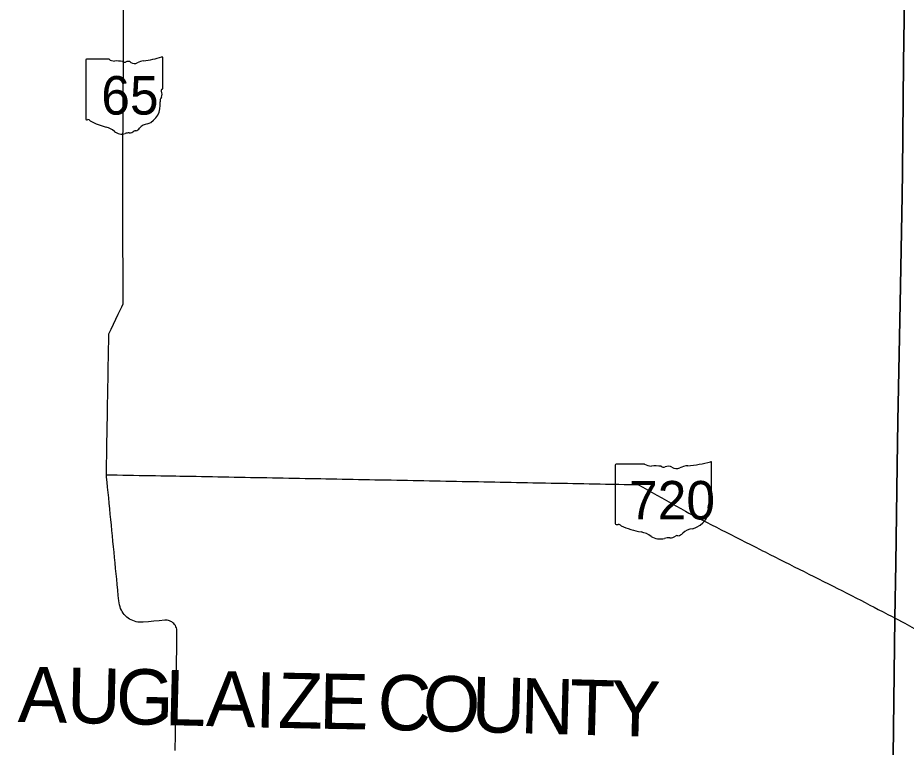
# Model space of a CAD drawing. Extents: x 0 to 34, y 0 to 22.
# Drawn here: x 6.011 to 6.269, y 19.3992 to 19.6111 of the extents above; entities that cross this region are included whole.
import ezdxf

# ---------------------------------------------------------------- set-up
doc = ezdxf.new("R2010")
doc.units = 0
for name, color, linetype in [('GM_X_County', 7, 'Continuous'), ('GM_X_County_Text', 7, 'Continuous'), ('GM_X_State_Location', 7, 'Continuous'), ('GM_X_State_Route', 7, 'Continuous'), ('GM_X_State_Shield', 7, 'Continuous')]:
    doc.layers.add(name, color=color, linetype=linetype)

msp = doc.modelspace()

# ---------------------------------------------------------------- linework, layer by layer
at = {"layer": 'GM_X_County'}
for points in [[(6.224545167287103, 19.175843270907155), (6.225083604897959, 19.219057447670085), (6.226321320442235, 19.304449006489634), (6.226424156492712, 19.311436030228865), (6.227034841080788, 19.389227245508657), (6.237472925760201, 19.389264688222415), (6.265053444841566, 19.38859652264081), (6.265712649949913, 19.43672940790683), (6.2660032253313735, 19.452577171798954), (6.266360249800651, 19.481082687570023), (6.2665922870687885, 19.493925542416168), (6.267210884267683, 19.52817666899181), (6.267798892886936, 19.559429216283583), (6.26790225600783, 19.566442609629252), (6.268171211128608, 19.597972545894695), (6.268916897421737, 19.643535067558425)], [(6.268916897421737, 19.643535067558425), (6.268171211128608, 19.597972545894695), (6.26790225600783, 19.566442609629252), (6.267798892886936, 19.559429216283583), (6.267210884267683, 19.52817666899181), (6.2665922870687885, 19.493925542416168), (6.266360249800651, 19.481082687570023), (6.2660032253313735, 19.452577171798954), (6.265712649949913, 19.43672940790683), (6.265053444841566, 19.38859652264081)]]:
    msp.add_lwpolyline(points, dxfattribs=at)
at = {"layer": 'GM_X_State_Route'}
for points in [[(6.056752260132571, 19.398250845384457), (6.056775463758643, 19.399832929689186), (6.056798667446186, 19.401415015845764), (6.056821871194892, 19.40299710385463), (6.056845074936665, 19.404579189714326), (6.056868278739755, 19.40616127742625), (6.056891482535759, 19.407743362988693), (6.0569146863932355, 19.40932545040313), (6.056937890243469, 19.410907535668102), (6.05696109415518, 19.41248962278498), (6.056984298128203, 19.414071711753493), (6.057007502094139, 19.415653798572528), (6.057030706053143, 19.41723588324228), (6.057053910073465, 19.418817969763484), (6.057077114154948, 19.420400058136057), (6.057100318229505, 19.421982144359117), (6.057123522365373, 19.423564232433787), (6.05714672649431, 19.425146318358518), (6.057169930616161, 19.426728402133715), (6.0571931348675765, 19.42831049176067), (6.057215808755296, 19.429892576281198), (6.057237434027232, 19.431362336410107), (6.057258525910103, 19.43283262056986), (6.057243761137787, 19.433197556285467), (6.05718891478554, 19.433558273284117), (6.057093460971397, 19.43391055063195), (6.0569595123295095, 19.434249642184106), (6.056788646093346, 19.434572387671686), (6.056582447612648, 19.434873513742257), (6.056344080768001, 19.435149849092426), (6.056076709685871, 19.435398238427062), (6.05578296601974, 19.435614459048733), (6.055467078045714, 19.435797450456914), (6.055132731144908, 19.435943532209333), (6.054784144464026, 19.436051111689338), (6.054425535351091, 19.436119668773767), (6.054061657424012, 19.436147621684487), (6.053696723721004, 19.43613443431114), (6.052121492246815, 19.435989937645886), (6.050546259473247, 19.43584544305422), (6.04898790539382, 19.43570252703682), (6.0474290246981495, 19.435560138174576), (6.046918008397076, 19.43553376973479), (6.046406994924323, 19.435548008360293), (6.045898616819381, 19.435603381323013), (6.045396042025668, 19.43569883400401), (6.044902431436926, 19.435833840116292), (6.044421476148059, 19.43600786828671), (6.043956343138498, 19.436219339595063), (6.043509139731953, 19.436467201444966), (6.0430830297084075, 19.43675039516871), (6.0426806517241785, 19.437066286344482), (6.042304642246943, 19.437413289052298), (6.041957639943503, 19.437788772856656), (6.041641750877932, 19.438191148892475), (6.0413590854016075, 19.438616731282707), (6.041110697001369, 19.439063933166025), (6.04089922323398, 19.439529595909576), (6.040725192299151, 19.440010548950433), (6.040566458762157, 19.440579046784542), (6.040447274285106, 19.441157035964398), (6.040369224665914, 19.441741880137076), (6.040214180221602, 19.443316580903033), (6.040059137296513, 19.44489128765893), (6.03990409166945, 19.446465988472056), (6.039749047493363, 19.448040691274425), (6.039594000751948, 19.449615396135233), (6.039438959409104, 19.451190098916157), (6.039283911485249, 19.452764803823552), (6.039128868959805, 19.45433950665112), (6.038973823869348, 19.455914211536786), (6.038818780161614, 19.45748891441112), (6.038663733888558, 19.459063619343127), (6.038508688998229, 19.460638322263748), (6.038353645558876, 19.462213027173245), (6.038198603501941, 19.46378773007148), (6.038043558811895, 19.465362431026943), (6.03788851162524, 19.466937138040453), (6.037732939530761, 19.468511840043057), (6.037577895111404, 19.470086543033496), (6.037422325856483, 19.471661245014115), (6.037267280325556, 19.473235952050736), (6.0371117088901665, 19.474810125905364), (6.036970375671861, 19.476245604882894), (6.036828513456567, 19.477681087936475), (6.036760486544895, 19.47837614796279), (6.036768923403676, 19.478866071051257), (6.036796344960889, 19.480448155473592), (6.03682376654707, 19.4820302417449), (6.036851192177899, 19.483612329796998), (6.036878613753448, 19.485194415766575), (6.036906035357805, 19.486776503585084), (6.0369334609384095, 19.488358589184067), (6.036960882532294, 19.489940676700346), (6.036988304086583, 19.491522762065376), (6.037015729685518, 19.49310484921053), (6.037043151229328, 19.494686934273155), (6.0370705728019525, 19.49626902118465), (6.037097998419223, 19.497851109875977), (6.037125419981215, 19.49943319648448), (6.037152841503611, 19.5010152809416), (6.037180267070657, 19.50259736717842), (6.037208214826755, 19.504179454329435), (6.037235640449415, 19.505761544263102), (6.03726358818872, 19.507343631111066), (6.037291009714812, 19.50892571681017), (6.037318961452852, 19.510507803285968), (6.037346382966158, 19.51208988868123), (6.037374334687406, 19.51367197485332), (6.037401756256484, 19.51525406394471), (6.037429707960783, 19.51683614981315), (6.0374508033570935, 19.51806173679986), (6.037472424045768, 19.519286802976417), (6.038155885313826, 19.520713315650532), (6.0388393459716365, 19.522139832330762), (6.039522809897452, 19.523566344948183), (6.040206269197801, 19.524992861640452), (6.040889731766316, 19.526419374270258), (6.0412667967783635, 19.527205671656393), (6.041643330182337, 19.527991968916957), (6.041635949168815, 19.529574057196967), (6.041628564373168, 19.531156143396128), (6.041621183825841, 19.532738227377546), (6.041613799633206, 19.534320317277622), (6.041606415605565, 19.53590240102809), (6.041599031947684, 19.537484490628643), (6.041591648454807, 19.539066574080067), (6.04158426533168, 19.54064866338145), (6.0415768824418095, 19.542230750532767), (6.041569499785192, 19.543812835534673), (6.041562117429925, 19.545394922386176), (6.041554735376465, 19.546977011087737), (6.0415478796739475, 19.548559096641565), (6.041540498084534, 19.550141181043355), (6.041533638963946, 19.551723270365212), (6.041526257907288, 19.553305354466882), (6.04151940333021, 19.554887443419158), (6.041512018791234, 19.556469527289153), (6.041505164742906, 19.558051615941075), (6.04149778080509, 19.559633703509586), (6.041490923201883, 19.561215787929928), (6.041487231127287, 19.564312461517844), (6.041498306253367, 19.565894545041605), (6.041509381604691, 19.567476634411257), (6.041520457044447, 19.56905872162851), (6.04153153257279, 19.570640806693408), (6.041542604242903, 19.572222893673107), (6.041553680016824, 19.573804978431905), (6.041564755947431, 19.575387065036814), (6.041575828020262, 19.576969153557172), (6.041586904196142, 19.578551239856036), (6.041597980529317, 19.580133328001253), (6.041609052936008, 19.58171541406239), (6.041620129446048, 19.5832974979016), (6.041631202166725, 19.584879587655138), (6.041642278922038, 19.586461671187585), (6.041653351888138, 19.588043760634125), (6.04166442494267, 19.58962584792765), (6.041675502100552, 19.591207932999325), (6.041686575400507, 19.592790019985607), (6.041697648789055, 19.594372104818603), (6.041708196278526, 19.595954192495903), (6.041719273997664, 19.597536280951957), (6.041729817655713, 19.599118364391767), (6.0417408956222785, 19.60070045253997), (6.041751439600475, 19.602282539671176), (6.041762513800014, 19.603864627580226), (6.041769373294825, 19.604840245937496), (6.041775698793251, 19.60581586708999), (6.041788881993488, 19.691094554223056)], [(6.036760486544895, 19.47837614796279), (6.03834257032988, 19.478349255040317), (6.039924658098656, 19.47832236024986), (6.041506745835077, 19.478295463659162), (6.043088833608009, 19.478268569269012), (6.04467091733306, 19.47824167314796), (6.046253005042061, 19.478214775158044), (6.047835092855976, 19.478187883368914), (6.049417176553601, 19.478160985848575), (6.050999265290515, 19.478134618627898), (6.052581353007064, 19.478107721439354), (6.054163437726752, 19.478081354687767), (6.055745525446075, 19.478054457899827), (6.056905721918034, 19.478034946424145), (6.058065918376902, 19.4780154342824), (6.059647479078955, 19.477985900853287), (6.061229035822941, 19.477956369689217), (6.062810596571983, 19.477926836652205), (6.064392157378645, 19.47789730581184), (6.065973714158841, 19.4778677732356), (6.0675552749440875, 19.477838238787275), (6.069136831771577, 19.477808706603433), (6.070718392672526, 19.477779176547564), (6.072299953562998, 19.477749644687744), (6.0738815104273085, 19.47772011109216), (6.075463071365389, 19.47769057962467), (6.077044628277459, 19.47766104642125), (6.078626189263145, 19.477631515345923), (6.080207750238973, 19.47760198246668), (6.081789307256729, 19.477572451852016), (6.083370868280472, 19.47754291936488), (6.084952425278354, 19.477513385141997), (6.086533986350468, 19.477483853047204), (6.088115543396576, 19.477454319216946), (6.08969710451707, 19.477424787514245), (6.09127866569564, 19.47739525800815), (6.092860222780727, 19.477365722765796), (6.094441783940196, 19.47733618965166), (6.096023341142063, 19.477306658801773), (6.097604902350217, 19.477277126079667), (6.099049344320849, 19.477250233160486), (6.100493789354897, 19.477222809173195), (6.102075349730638, 19.477192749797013), (6.1036569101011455, 19.47716268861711), (6.105238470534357, 19.47713262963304), (6.106820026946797, 19.4771025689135), (6.108401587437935, 19.47707251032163), (6.109983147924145, 19.477042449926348), (6.11156470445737, 19.4770123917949), (6.113146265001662, 19.476982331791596), (6.114727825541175, 19.476952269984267), (6.116309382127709, 19.476922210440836), (6.1178909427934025, 19.476892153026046), (6.119472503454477, 19.476862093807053), (6.121054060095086, 19.476832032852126), (6.122635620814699, 19.47680197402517), (6.12421718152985, 19.476771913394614), (6.125798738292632, 19.476741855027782), (6.12738029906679, 19.476711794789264), (6.128961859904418, 19.47668173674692), (6.130543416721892, 19.47665167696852), (6.1321249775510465, 19.476621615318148), (6.133706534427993, 19.47659155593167), (6.135288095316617, 19.47656149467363), (6.136869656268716, 19.476531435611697), (6.138451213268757, 19.476501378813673), (6.140032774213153, 19.476471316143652), (6.141614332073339, 19.476441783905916), (6.143195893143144, 19.47641172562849), (6.144777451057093, 19.476382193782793), (6.146359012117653, 19.476352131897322), (6.147940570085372, 19.47632260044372), (6.149522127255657, 19.476292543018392), (6.151103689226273, 19.47626300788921), (6.152685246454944, 19.47623295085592), (6.154266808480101, 19.476203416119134), (6.155848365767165, 19.476173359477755), (6.157429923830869, 19.476143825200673), (6.159011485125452, 19.476113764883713), (6.160593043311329, 19.476084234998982), (6.16217460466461, 19.476054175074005), (6.163230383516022, 19.476034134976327), (6.1642861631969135, 19.476014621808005), (6.165867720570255, 19.475984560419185), (6.167449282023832, 19.475954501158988), (6.169030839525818, 19.4759244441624), (6.170612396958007, 19.47589438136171), (6.172193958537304, 19.475864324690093), (6.173775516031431, 19.47583426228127), (6.17535707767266, 19.475804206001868), (6.176938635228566, 19.475774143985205), (6.178520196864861, 19.475744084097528), (6.180101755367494, 19.475714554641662), (6.181683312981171, 19.475684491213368), (6.183264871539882, 19.47565496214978), (6.184411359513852, 19.475633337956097), (6.1855578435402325, 19.475611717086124), (6.187139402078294, 19.475582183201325), (6.188720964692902, 19.47555265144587), (6.18990541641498, 19.47553050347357), (6.191089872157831, 19.475508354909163), (6.192471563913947, 19.47473787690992), (6.193853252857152, 19.47396740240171), (6.195234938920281, 19.473196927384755), (6.196616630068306, 19.472426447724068), (6.19799831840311, 19.471655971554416), (6.199380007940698, 19.470885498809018), (6.200761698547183, 19.47011502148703), (6.202143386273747, 19.469344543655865), (6.203525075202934, 19.468574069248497), (6.204907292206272, 19.467804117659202), (6.205861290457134, 19.467272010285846), (6.206815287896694, 19.466740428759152), (6.208225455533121, 19.466022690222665), (6.209635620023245, 19.46530495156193), (6.211045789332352, 19.46458720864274), (6.2124559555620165, 19.463869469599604), (6.213866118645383, 19.463151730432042), (6.2152762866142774, 19.462433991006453), (6.216686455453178, 19.461716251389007), (6.218096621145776, 19.46099851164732), (6.219506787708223, 19.460280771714), (6.2209169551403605, 19.45956303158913), (6.222327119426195, 19.45884529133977), (6.223737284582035, 19.458127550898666), (6.22514745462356, 19.457409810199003), (6.226557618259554, 19.456692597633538), (6.227287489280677, 19.456320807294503), (6.228017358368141, 19.455949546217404), (6.229430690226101, 19.455238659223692), (6.230844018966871, 19.45452777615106), (6.232257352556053, 19.45381689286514), (6.233670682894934, 19.45310600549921), (6.23508401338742, 19.452394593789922), (6.236497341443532, 19.451683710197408), (6.237910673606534, 19.450972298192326), (6.239324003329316, 19.450261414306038), (6.24073733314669, 19.44955000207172), (6.242150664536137, 19.44883911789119), (6.243563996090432, 19.448127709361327), (6.2449773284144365, 19.447416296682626), (6.246390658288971, 19.446705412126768), (6.247803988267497, 19.445993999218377), (6.2490490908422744, 19.445367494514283), (6.250294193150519, 19.44474098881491), (6.251703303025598, 19.444021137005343), (6.25177744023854, 19.44398325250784)], [(6.25177744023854, 19.44398325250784), (6.253111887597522, 19.443301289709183), (6.254521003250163, 19.442581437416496), (6.255787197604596, 19.441934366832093), (6.257053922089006, 19.441287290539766), (6.258450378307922, 19.44054424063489), (6.259660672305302, 19.439900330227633), (6.260871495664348, 19.439255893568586), (6.262276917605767, 19.438529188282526), (6.263682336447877, 19.437802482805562), (6.264679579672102, 19.43728725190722), (6.265766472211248, 19.43675672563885)], [(6.265766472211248, 19.43675672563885), (6.2685720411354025, 19.435230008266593), (6.271969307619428, 19.433355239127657)]]:
    msp.add_lwpolyline(points, dxfattribs=at)
at = {"layer": 'GM_X_State_Shield'}
for p, q in [((6.030746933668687, 19.59879273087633), (6.030746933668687, 19.581808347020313)), ((6.037520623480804, 19.59908496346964), (6.030967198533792, 19.59908496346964)), ((6.053124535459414, 19.590621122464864), (6.053124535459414, 19.59950586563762)), ((6.0531223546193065, 19.59062330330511), (6.053124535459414, 19.590621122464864)), ((6.192994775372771, 19.481468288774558), (6.184802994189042, 19.481468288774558)), ((6.212499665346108, 19.47300444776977), (6.212499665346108, 19.481889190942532)), ((6.184527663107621, 19.481176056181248), (6.184527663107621, 19.46419167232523)), ((6.212496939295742, 19.473006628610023), (6.212499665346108, 19.47300444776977))]:
    msp.add_line(p, q, dxfattribs=at)
for centre, radius, start, end in [((6.0310032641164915, 19.59882889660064), 0.0002592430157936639, 98.1301027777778, 188.13010277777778), ((6.039081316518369, 19.601056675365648), 0.0025145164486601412, 231.61950555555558, 271.11188333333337), ((6.039915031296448, 19.58954973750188), 0.009027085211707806, 80.48669166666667, 94.98826944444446), ((6.041964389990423, 19.598916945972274), 0.0007254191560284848, 219.79206111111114, 297.1023694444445), ((6.043029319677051, 19.59695387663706), 0.0015082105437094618, 54.466683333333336, 119.14113055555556), ((6.044975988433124, 19.599646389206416), 0.0018143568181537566, 233.85620555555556, 294.82819166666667), ((6.0481802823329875, 19.593897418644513), 0.004774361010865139, 97.34618055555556, 120.7688527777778), ((6.045153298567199, 19.622240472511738), 0.02373123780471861, 275.8444694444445, 288.9064527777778), ((6.052876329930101, 19.599542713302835), 0.000249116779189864, 351.8620861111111, 97.738), ((6.053066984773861, 19.5899688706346), 0.00038552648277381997, 107.94398333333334, 210.33696666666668), ((6.050614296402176, 19.588845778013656), 0.002314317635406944, 340.0329638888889, 23.649566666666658), ((6.052858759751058, 19.59058679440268), 0.0002666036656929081, 289.6038111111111, 7.734130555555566), ((6.054017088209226, 19.58690296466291), 0.001683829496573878, 136.80649722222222, 186.92959444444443), ((6.046482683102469, 19.58577270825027), 0.005935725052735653, 292.3088861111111, 8.985838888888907), ((6.03100559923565, 19.58177116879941), 0.00026154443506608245, 171.9583861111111, 258.30661388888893), ((6.031045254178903, 19.58350880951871), 0.0019959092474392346, 267.33899444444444, 280.6038555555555), ((6.031453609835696, 19.58082847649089), 0.000719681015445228, 29.748380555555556, 93.27174722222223), ((6.040539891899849, 19.59608823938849), 0.017137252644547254, 240.41292222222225, 257.1985), ((6.035430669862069, 19.57417805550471), 0.0053619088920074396, 47.184155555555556, 75.83597222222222), ((6.048985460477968, 19.577040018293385), 0.0032508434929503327, 94.40312222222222, 142.57675), ((6.041229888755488, 19.580744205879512), 0.003402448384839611, 230.70037222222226, 286.29183611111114), ((6.043195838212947, 19.574872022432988), 0.0027957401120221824, 85.69512222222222, 111.20994722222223), ((6.043444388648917, 19.579472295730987), 0.0018128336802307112, 268.7770194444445, 315.54927222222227), ((6.045084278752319, 19.577827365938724), 0.0005103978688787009, 65.75173055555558, 132.64842222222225), ((6.044866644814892, 19.58016222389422), 0.0019176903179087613, 282.8731916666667, 323.27711111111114)]:
    msp.add_arc(centre, radius, start, end, dxfattribs=at)
for centre, major_axis, ratio, start_param, end_param in [((6.184848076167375, 19.48121222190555), (0.00032405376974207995, 0), 0.7999999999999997, 1.7126933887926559, 3.283489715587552), ((6.194945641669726, 19.48344000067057), (0.0031431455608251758, 0), 0.8000000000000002, 4.042522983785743, 4.731795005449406), ((6.2025356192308, 19.504623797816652), (0.029664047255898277, 0), 0.7999999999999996, 4.81439421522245, 5.042368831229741), ((6.212189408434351, 19.481926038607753), (0.00031139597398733, 0), 0.8000000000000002, 6.141151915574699, 7.989035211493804), ((6.1959877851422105, 19.47193306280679), (0.011283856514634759, 0), 0.7999999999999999, 1.4047577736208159, 1.6578580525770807), ((6.198549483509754, 19.481300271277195), (0.0009067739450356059, 0), 0.8, 3.836095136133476, 5.185414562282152), ((6.199880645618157, 19.479337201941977), (0.001885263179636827, 0), 0.8000000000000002, 0.9506229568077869, 2.0794050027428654), ((6.202313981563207, 19.482029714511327), (0.0022679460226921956, 0), 0.8, 4.0815607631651, 5.145722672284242), ((6.20631934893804, 19.476280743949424), (0.005967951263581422, 0), 0.8000000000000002, 1.6990113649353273, 2.107814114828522), ((6.212427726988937, 19.472352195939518), (0.0004819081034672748, 0), 0.8000000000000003, 1.8839779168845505, 3.671072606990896), ((6.2093618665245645, 19.471229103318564), (0.00289289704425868, 0), 0.8, 5.934694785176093, 6.69594811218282), ((6.2121674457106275, 19.472970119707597), (0.0003332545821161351, 0), 0.8, 5.054540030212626, 6.418171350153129), ((6.204197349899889, 19.46815603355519), (0.007419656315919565, 0), 0.8000000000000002, 5.1017524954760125, 6.440017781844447), ((6.213615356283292, 19.46928628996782), (0.0021047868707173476, 0), 0.7999999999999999, 2.3877238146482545, 3.2625368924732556), ((6.184850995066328, 19.464154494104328), (0.00032693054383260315, 0), 0.7999999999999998, 3.0012400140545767, 4.508300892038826), ((6.184900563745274, 19.46589213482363), (0.0024948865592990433, 0), 0.8, 4.6659456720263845, 4.897461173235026), ((6.185411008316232, 19.463211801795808), (0.0008996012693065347, 0), 0.8000000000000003, 0.5192071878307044, 1.6278990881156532), ((6.196768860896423, 19.4784715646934), (0.02142156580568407, 0), 0.7999999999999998, 4.195997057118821, 4.488960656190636), ((6.190382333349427, 19.456561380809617), (0.006702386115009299, 0), 0.8, 0.8235188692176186, 1.3235874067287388), ((6.202449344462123, 19.46021069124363), (0.000637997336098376, 0), 0.8000000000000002, 1.1475841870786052, 2.315151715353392), ((6.2021773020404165, 19.46254554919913), (0.002397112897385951, 0), 0.8000000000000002, 4.93706856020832, 5.642249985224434), ((6.207325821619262, 19.459423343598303), (0.004063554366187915, 0), 0.8000000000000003, 1.6476453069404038, 2.4884337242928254), ((6.197631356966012, 19.46312753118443), (0.004253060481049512, 0), 0.8000000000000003, 4.0264810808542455, 4.996735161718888), ((6.200088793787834, 19.457255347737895), (0.003494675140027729, 0), 0.7999999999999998, 1.4956620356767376, 1.9409797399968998), ((6.200399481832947, 19.461855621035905), (0.002266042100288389, 0), 0.8, 4.691043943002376, 5.507373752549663)]:
    msp.add_ellipse(centre, major_axis=major_axis, ratio=ratio, start_param=start_param, end_param=end_param, dxfattribs=at)

# ---------------------------------------------------------------- texts
at = {"layer": 'GM_X_County_Text'}
for s, height, rotation, p in [('A', 0.016074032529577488, 358.779037, (6.0109879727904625, 19.40661504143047)), ('U', 0.01607403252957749, 358.77333, (6.025200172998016, 19.40631213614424)), ('G', 0.016074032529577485, 358.71759099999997, (6.039408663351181, 19.406007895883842)), ('L', 0.016074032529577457, 358.59075, (6.053611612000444, 19.4056899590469)), ('A', 0.016074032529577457, 358.51173, (6.065625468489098, 19.40539440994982)), ('I', 0.016074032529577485, 358.65677, (6.079847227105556, 19.405024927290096)), ('Z', 0.016074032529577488, 358.85889000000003, (6.086437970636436, 19.404870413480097)), ('E', 0.016074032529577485, 358.960144, (6.098466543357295, 19.40463082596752)), ('C', 0.016074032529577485, 358.713295, (6.115348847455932, 19.404320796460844)), ('O', 0.016074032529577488, 358.57347500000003, (6.128419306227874, 19.40402723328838)), ('U', 0.016074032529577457, 358.507382, (6.142625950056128, 19.403673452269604)), ('N', 0.016074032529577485, 358.49488099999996, (6.156836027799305, 19.403303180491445)), ('T', 0.016074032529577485, 358.493004, (6.17104689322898, 19.402929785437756)), ('Y', 0.016074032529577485, 358.492707, (6.183066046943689, 19.402613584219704))]:
    msp.add_text(s, height=height, rotation=rotation, dxfattribs=at).set_placement(p)
at = {"layer": 'GM_X_State_Location'}
for s, p in [('65', (6.037635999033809, 19.588001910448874)), ('720', (6.19252496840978, 19.470385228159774))]:
    msp.add_text(s, height=1.6074032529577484e-05, rotation=1.0000000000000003e-05, dxfattribs=at).set_placement(p)
for s, p in [('s', (6.041683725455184, 19.589171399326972)), ('r', (6.041682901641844, 19.589171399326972)), ('s', (6.198199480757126, 19.47155472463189)), ('r', (6.198198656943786, 19.47155472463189))]:
    msp.add_text(s, height=1.6074032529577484e-05, dxfattribs=at).set_placement(p)
at = {"layer": 'GM_X_State_Shield'}
for s, height, p in [('65', 0.011189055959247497, (6.0352711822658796, 19.583006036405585)), ('720', 0.011189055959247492, (6.188512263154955, 19.465389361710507))]:
    msp.add_text(s, height=height, dxfattribs=at).set_placement(p)

doc.saveas('drawing.dxf')
